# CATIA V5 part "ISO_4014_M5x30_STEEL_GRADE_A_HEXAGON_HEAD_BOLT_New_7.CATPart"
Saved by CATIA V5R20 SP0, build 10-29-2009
Part number: ISO 4014 BOLT M5x30 STEEL GRADE A HEXAGON HEAD.5
Publications: "Mating Face", "Axis"
Bounding box of the stored display mesh (mm): x -30 to 3.65, y -4 to 4, z -4.619 to 4.619
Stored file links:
  E:\设计\180212313林恺昇\ISO_4014_M5x30_STEEL_GRADE_A_HEXAGON_HEAD_BOLT_New_7.CATPart
  d:\Dassault Systemes\B20\win_b64\startup\components\MechanicalStandardParts\EN_Standards\Design_Tables\EN_ISO_4014_GRADES_A_B_HEXAGON_HEAD_BOLT.txt
  C:\Program Files\Dassault Systemes\B20\intel_a\startup\components\MechanicalStandardParts\ISO_Standards\Design_Tables\ISO_4014_GRADES_A_B_HEXAGON_HEAD_BOLT.txt
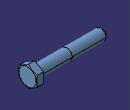
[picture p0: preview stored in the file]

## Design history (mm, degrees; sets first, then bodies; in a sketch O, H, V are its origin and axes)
Parameters
  d_dia = 5 mm
  l_length = 30 mm
  s_nom_across_flats = 8 mm
  k_max_head_depth = 3.65 mm
  dw_min = 6.88 mm
  r_min = 0.2 mm
  c_max = 0.5 mm
  p_pitch = 0.8 mm
  threading = 16 mm
Body1 "PartBody" (main body)
  Sketch1 on yz-plane, origin (0, 0, 0), H (0, 1, 0), V (0, 0, 1)
    circle A1 centre (0, 0) radius 3.44
    radius A1 = 3.44 {= dw_min /2}
  Pad1: profile Sketch1, direction (1, 0, 0), length 0.5 {= c_max}
  Sketch2 on face of Pad1, origin (0.5, 0, 0), H (0, 1, 0), V (0, 0, 1)
    point P1 (4, -2.3094)
    point P2 (4, 2.3094)
    point P3 (0, 4.6188)
    point P4 (-4, 2.3094)
    point P5 (-4, -2.3094)
    point P6 (0, -4.6188)
    point P7 (4, 0)
    line L1 (4, -2.3094) -> (4, 2.3094)
    line L2 (4, 2.3094) -> (0, 4.6188)
    line L3 (0, 4.6188) -> (-4, 2.3094)
    line L4 (-4, 2.3094) -> (-4, -2.3094)
    line L5 (-4, -2.3094) -> (0, -4.6188)
    line L6 (0, -4.6188) -> (4, -2.3094)
    construction line L7 (0, 0) -> (4, 0)
    construction circle A1 centre (0, 0) radius 4.6188
    construction arc A2 centre (-4, -2.3094) radius 4.6188 from (-4, 2.3094) to (0, -4.6188) cw
    construction arc A3 centre (4, 2.3094) radius 4.6188 from (0, 4.6188) to (4, -2.3094) ccw
    point P8 (-4, -2.3094)
    point P9 (4, 2.3094)
    distance L1 L4 = 8 {= s_nom_across_flats}
    horizontal: L7 H
    coincidence: A1 P1, A1 P2, A1 P3, A1 P4, A1 P5, A1 P6, A2 P4, A2 P6, A2 O, P8 P5, A3 P3, A3 P1, A3 O, P9 P2
    midpoint: P7 L1
  Pad2: profile Sketch2, direction (1, 0, 0), length 3.15 {= k_max_head_depth -c_max}
  Sketch3 on zx-plane, origin (0, 0, 0), H (-1, 0, 0), V (0, 0, 1)
    point P1 (-3.65, 3.9821)
    axis line L1 (-94.6904, 0) -> (76.7146, 0)
    reference intersected line E1 through (1000000, 0) direction (-1, 0) from xy-plane
    line L2 (-3.2824, 4.6188) -> (-3.65, 3.9821)
    line L3 (-3.2824, 4.6188) -> (-3.65, 4.6188)
    line L4 (-3.65, 4.6188) -> (-3.65, 3.9821)
    reference projected line E2 (-0.8, 4.6188) -> (-18.28, 4.6188) from edge [face of Pad2 | face of Pad2]
    distance P1 H = 3.9821 {= s_nom_across_flats /2.009}
    distance P1 V = 3.65 {= k_max_head_depth}
    angle L4 L2 = 30
    horizontal: L1 H, L3 H
    coincidence: L1 E1, L3 E2
    vertical: L4 V
  Groove1: profile Sketch3, axis Sketch3.L1, angle 360
  Sketch4 on face of Pad1, origin (0, 0, 0), H (0, -1, 0), V (0, 0, 1)
    circle A1 centre (0, 0) radius 2.5
    radius A1 = 2.5 {= d_dia /2}
  Pad3: profile Sketch4, direction (-1, 0, 0), length 14 {= l_length -threading}
  Sketch5 on face of Pad3, origin (-14, 0, 0), H (0, -1, 0), V (0, 0, 1)
    circle A1 centre (0, 0) radius 2.439
    radius A1 = 2.439 {= d_dia /2.05}
  Pad4: profile Sketch5, direction (-1, 0, 0), length 16 {= threading}
  Chamfer1: length 0.8 {= p_pitch}, angle 45, on face of Pad4
  Fillet1: radius 0.2 {= r_min}, on edge [face of Pad3 | face of Pad1]
  Thread1: diameter 4.878 {= d_dia /1.025}, depth 16 {= threading}, pitch 1, on face of Pad4, from face of Pad4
